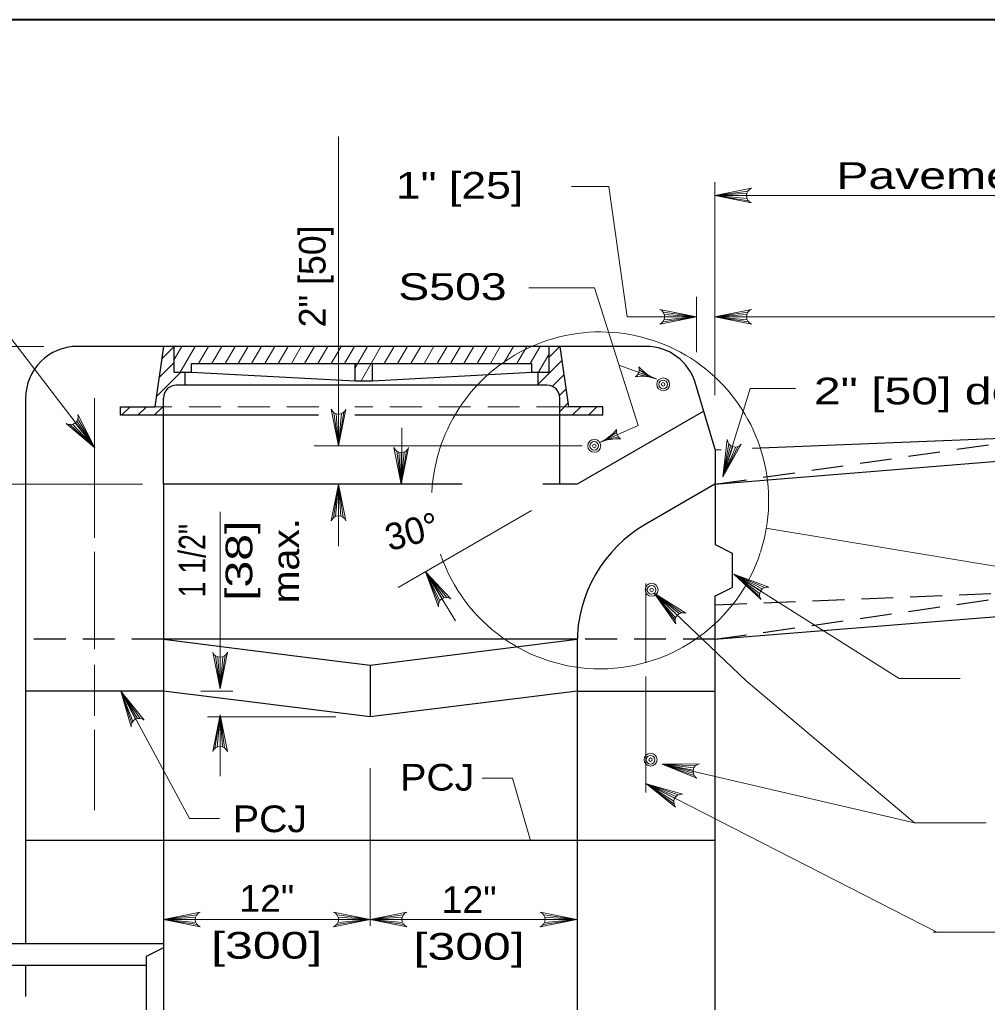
# Model space of a CAD drawing. Extents: x 758.3 to 792.3, y 849.7 to 893.7.
# Drawn here: x 764.35 to 770.01, y 865.44 to 871.19 of the extents above; entities that cross this region are included whole.
import ezdxf
from ezdxf.enums import TextEntityAlignment as Align

# ---------------------------------------------------------------- set-up
doc = ezdxf.new("R2010")
doc.units = 0
doc.header["$LTSCALE"] = 0.062
doc.linetypes.add('MEDIUM_DASHED', pattern=[4.5, 3, -1.5])
doc.layers.add('1', color=7, linetype='Continuous', lineweight=13)

msp = doc.modelspace()

# ---------------------------------------------------------------- linework, layer by layer
at = {"layer": '1', "lineweight": 25}
for p, q in [((760.3205, 871.18817), (791.8205, 871.18817)), ((768.01208, 869.27742), (764.68608, 869.27742)), ((765.19, 869.27742), (765.13967, 868.92475)), ((765.253, 869.12625), (765.253, 869.27742)), ((767.44517, 869.12625), (767.44517, 869.27742)), ((767.50808, 869.27742), (767.5585, 868.92475)), ((765.35383, 869.12625), (765.35383, 869.17667)), ((765.35383, 869.17667), (767.34433, 869.17667)), ((766.31125, 869.07592), (766.31125, 869.17667)), ((766.41208, 869.07592), (766.41208, 869.17667)), ((767.34433, 869.12625), (767.34433, 869.17667)), ((765.316, 869.05067), (765.316, 869.12625)), ((765.35383, 869.12625), (766.31125, 869.07592)), ((766.41208, 869.07592), (767.34433, 869.12625)), ((767.38217, 869.05067), (767.38217, 869.12625)), ((767.4325, 869.05067), (765.26567, 869.05067)), ((766.31125, 869.07592), (766.41208, 869.07592)), ((768.41617, 868.6735), (768.30208, 869.06058)), ((764.38375, 868.97508), (764.38375, 865.78567)), ((765.19, 868.87433), (765.19, 868.97508)), ((767.50808, 868.87433), (767.50808, 868.97508)), ((764.93808, 868.87433), (764.93808, 868.92475)), ((764.93808, 868.92475), (765.13967, 868.92475)), ((766.096, 868.87433), (764.93808, 868.87433)), ((765.19, 868.47125), (765.19, 868.87433)), ((767.76008, 868.87433), (766.30983, 868.87433)), ((767.50808, 868.47125), (767.50808, 868.87433)), ((767.76008, 868.92475), (767.5585, 868.92475)), ((768.34992, 868.89892), (767.60908, 868.47125)), ((767.76008, 868.87433), (767.76008, 868.92475)), ((768.41517, 868.47117), (773.37233, 868.87425)), ((768.6345, 868.68158), (773.37233, 868.87425)), ((768.41517, 868.67267), (768.45258, 868.67425)), ((768.41617, 868.6735), (768.41617, 868.118)), ((765.19, 868.47125), (765.19, 864.39992)), ((766.9375, 868.47125), (765.19, 868.47125)), ((767.60908, 868.47125), (767.40967, 868.47125)), ((768.41517, 868.47117), (768.01208, 868.23842)), ((768.41617, 868.118), (768.516, 868.06817)), ((768.516, 868.06817), (768.516, 867.86658)), ((768.41517, 867.56425), (772.36417, 867.88542)), ((768.41517, 867.81617), (768.516, 867.86658)), ((768.41517, 867.81617), (768.41517, 863.59375)), ((767.60892, 867.56425), (765.19, 867.56425)), ((766.39933, 867.41308), (767.60892, 867.56425)), ((767.60892, 867.54017), (767.60892, 864.39992)), ((766.39933, 867.41308), (766.39933, 867.11075)), ((765.19, 867.26192), (764.38342, 867.26192)), ((766.3995, 867.11075), (765.19, 867.26192)), ((767.60892, 867.26192), (766.39933, 867.11075)), ((767.60892, 867.26192), (768.41525, 867.26192)), ((764.38375, 866.39033), (768.41517, 866.39033)), ((763.47508, 865.78567), (765.19, 865.78567)), ((765.19, 865.7605), (765.08925, 865.71008)), ((763.47333, 865.65958), (765.08925, 865.65958)), ((765.08925, 865.71008), (765.08925, 864.3495))]:
    msp.add_line(p, q, dxfattribs=at)
at = {"layer": '1'}
for p, q in [((766.214, 868.69567), (766.214, 870.5045)), ((767.79483, 870.21275), (767.57708, 870.21275)), ((767.90183, 869.451), (767.79483, 870.21275)), ((768.41517, 868.99158), (768.41517, 870.23767)), ((768.60908, 870.18608), (768.41517, 870.159)), ((768.6025, 870.17267), (768.41517, 870.159)), ((768.6005, 870.159), (768.41517, 870.159)), ((768.60392, 870.14158), (768.41517, 870.159)), ((768.61133, 870.129), (768.41517, 870.159)), ((768.41517, 870.159), (773.37233, 870.159)), ((767.71108, 869.61917), (767.32633, 869.61917)), ((768.30667, 869.24317), (768.30667, 869.56742)), ((767.90183, 869.451), (768.30667, 869.451)), ((768.1105, 869.421), (768.30667, 869.451)), ((768.11275, 869.47808), (768.30667, 869.451)), ((768.11792, 869.43358), (768.30667, 869.451)), ((768.11933, 869.46467), (768.30667, 869.451)), ((768.12133, 869.451), (768.30667, 869.451)), ((768.60908, 869.47808), (768.41517, 869.451)), ((768.6025, 869.46467), (768.41517, 869.451)), ((768.41517, 869.451), (773.1385, 869.451)), ((768.6005, 869.451), (768.41517, 869.451)), ((768.60392, 869.43358), (768.41517, 869.451)), ((768.61133, 869.421), (768.41517, 869.451)), ((764.49067, 869.27742), (762.63192, 869.27742)), ((765.17958, 869.204), (765.253, 869.27742)), ((765.253, 869.19983), (765.29792, 869.27742)), ((765.28817, 869.12625), (765.3755, 869.27742)), ((765.39492, 869.17667), (765.45308, 869.27742)), ((765.47242, 869.17667), (765.53067, 869.27742)), ((765.55008, 869.17667), (765.60833, 869.27742)), ((765.62767, 869.17667), (765.68592, 869.27742)), ((765.70525, 869.17667), (765.7635, 869.27742)), ((765.78283, 869.17667), (765.841, 869.27742)), ((765.8605, 869.17667), (765.91858, 869.27742)), ((765.93808, 869.17667), (765.99625, 869.27742)), ((766.01558, 869.17667), (766.07375, 869.27742)), ((766.09317, 869.17667), (766.15133, 869.27742)), ((766.17075, 869.17667), (766.22892, 869.27742)), ((766.24833, 869.17667), (766.30658, 869.27742)), ((766.31125, 869.1515), (766.38408, 869.27742)), ((766.34533, 869.07592), (766.46167, 869.27742)), ((766.48108, 869.17667), (766.53925, 869.27742)), ((766.55858, 869.17667), (766.61683, 869.27742)), ((766.63625, 869.17667), (766.6945, 869.27742)), ((766.71383, 869.17667), (766.77208, 869.27742)), ((766.79142, 869.17667), (766.84958, 869.27742)), ((766.869, 869.17667), (766.92717, 869.27742)), ((766.94667, 869.17667), (767.00475, 869.27742)), ((767.02417, 869.17667), (767.08242, 869.27742)), ((767.10175, 869.17667), (767.15992, 869.27742)), ((767.17933, 869.17667), (767.23758, 869.27742)), ((767.25692, 869.17667), (767.31508, 869.27742)), ((767.33458, 869.17667), (767.39275, 869.27742)), ((767.44492, 869.21425), (767.50808, 869.27742)), ((767.38308, 869.12625), (767.44517, 869.23367)), ((765.16375, 869.09325), (765.253, 869.1825)), ((767.382, 869.05633), (767.52, 869.19433)), ((768.0735, 869.08675), (767.85358, 869.16842)), ((765.14792, 868.98225), (765.29183, 869.12625)), ((767.46358, 869.04292), (767.53192, 869.11125)), ((767.50808, 868.99242), (767.54367, 869.02808)), ((768.46392, 868.51933), (768.62125, 869.03017)), ((768.62125, 869.03017), (768.88725, 869.03017)), ((764.78692, 868.97508), (764.78692, 868.15833)), ((767.50808, 868.89742), (767.55567, 868.945)), ((764.94492, 868.87433), (764.99533, 868.92475)), ((765.03983, 868.87433), (765.09025, 868.92475)), ((765.135, 868.87433), (765.1855, 868.92475)), ((766.18683, 868.88958), (766.214, 868.69567)), ((766.20025, 868.883), (766.214, 868.69567)), ((766.24392, 868.89183), (766.214, 868.69567)), ((766.23142, 868.88442), (766.214, 868.69567)), ((766.214, 868.881), (766.214, 868.69567)), ((767.581, 868.87533), (767.63033, 868.92475)), ((767.67608, 868.87533), (767.7255, 868.92475)), ((764.64275, 868.82008), (764.78783, 868.68458)), ((764.65725, 868.822), (764.78783, 868.68458)), ((764.673, 868.83008), (764.78783, 868.68458)), ((764.68258, 868.84017), (764.78783, 868.68458)), ((764.689, 868.85367), (764.78783, 868.68458)), ((766.58425, 868.47108), (766.58425, 868.80192)), ((768.49633, 868.708), (768.46167, 868.51525)), ((767.63825, 868.69567), (766.07108, 868.69567)), ((766.55392, 868.66517), (766.581, 868.47125)), ((766.56733, 868.65858), (766.581, 868.47125)), ((766.611, 868.66742), (766.581, 868.47125)), ((766.59842, 868.66), (766.581, 868.47125)), ((766.581, 868.65658), (766.581, 868.47125)), ((768.50708, 868.6975), (768.46167, 868.51525)), ((768.55133, 868.69233), (768.46167, 868.51525)), ((768.5195, 868.69133), (768.46167, 868.51525)), ((768.53708, 868.68917), (768.46167, 868.51525)), ((768.50567, 868.62108), (768.46167, 868.51525)), ((765.06675, 868.47125), (763.33992, 868.47125)), ((766.184, 868.27508), (766.214, 868.47125)), ((766.19658, 868.2825), (766.214, 868.47125)), ((766.214, 868.28592), (766.214, 868.47125)), ((766.22767, 868.28392), (766.214, 868.47125)), ((766.24108, 868.27733), (766.214, 868.47125)), ((766.214, 868.46083), (766.214, 868.10958)), ((765.52067, 867.27408), (765.52067, 868.30892)), ((767.34208, 868.31717), (766.56267, 867.86717)), ((768.71325, 868.21517), (772.67008, 867.555)), ((764.78692, 868.07683), (764.78692, 867.50583)), ((766.81967, 867.80217), (766.72208, 867.95975)), ((766.80667, 867.79008), (766.72208, 867.95975)), ((766.79983, 867.77717), (766.72208, 867.95975)), ((766.83233, 867.80767), (766.72208, 867.95975)), ((766.84725, 867.80917), (766.72208, 867.95975)), ((766.72275, 867.95908), (766.89783, 867.67242)), ((768.68333, 867.84808), (768.52592, 867.94592)), ((768.677, 867.8315), (768.52592, 867.94592)), ((768.67675, 867.81692), (768.52592, 867.94592)), ((768.69225, 867.85867), (768.52592, 867.94592)), ((768.70492, 867.86667), (768.52592, 867.94592)), ((768.01208, 867.89033), (768.01208, 867.42617)), ((768.19467, 867.70575), (768.06042, 867.8335)), ((768.18508, 867.69075), (768.06042, 867.8335)), ((768.18183, 867.67658), (768.06042, 867.8335)), ((768.20558, 867.71433), (768.06042, 867.8335)), ((768.21958, 867.7195), (768.06042, 867.8335)), ((765.49358, 867.468), (765.52067, 867.27408)), ((765.507, 867.46142), (765.52067, 867.27408)), ((765.55067, 867.47025), (765.52067, 867.27408)), ((765.53808, 867.46283), (765.52067, 867.27408)), ((765.52067, 867.45942), (765.52067, 867.27408)), ((764.78692, 867.41508), (764.78692, 867.116)), ((768.01208, 867.346), (768.01208, 866.66817)), ((765.02558, 867.09708), (764.941, 867.262)), ((765.01167, 867.08608), (764.941, 867.262)), ((765.00392, 867.07375), (764.941, 867.262)), ((765.03875, 867.10158), (764.941, 867.262)), ((765.05367, 867.10183), (764.941, 867.262)), ((765.59633, 867.26192), (765.40842, 867.26192)), ((766.19717, 867.11075), (765.44733, 867.11075)), ((765.49067, 866.92675), (765.52067, 867.12292)), ((765.50325, 866.93417), (765.52067, 867.12292)), ((765.52067, 866.76467), (765.52067, 867.12292)), ((765.52067, 866.93758), (765.52067, 867.12292)), ((765.53442, 866.93558), (765.52067, 867.12292)), ((765.54783, 866.929), (765.52067, 867.12292)), ((764.78692, 867.0345), (764.78692, 866.56508)), ((766.3995, 866.81033), (766.3995, 865.88942)), ((768.28817, 866.79975), (768.10608, 866.83392)), ((768.28833, 866.782), (768.10608, 866.83392)), ((768.29333, 866.76825), (768.10608, 866.83392)), ((768.29267, 866.81283), (768.10608, 866.83392)), ((768.30158, 866.82483), (768.10608, 866.83392)), ((768.10608, 866.83392), (769.582, 866.49083)), ((768.01367, 866.721), (769.71275, 865.85208)), ((768.17975, 866.63458), (768.01533, 866.72)), ((768.17475, 866.6175), (768.01533, 866.72)), ((768.17558, 866.60292), (768.01533, 866.72)), ((768.18783, 866.64583), (768.01533, 866.72)), ((768.19992, 866.65467), (768.01533, 866.72)), ((769.582, 866.49083), (770.00233, 866.49083)), ((765.38408, 865.95325), (765.19017, 865.92608)), ((766.20508, 865.95333), (766.399, 865.92617)), ((766.59292, 865.95333), (766.399, 865.92617)), ((767.41358, 865.95325), (767.6075, 865.92608)), ((765.3775, 865.93983), (765.19017, 865.92608)), ((765.3755, 865.92608), (765.19017, 865.92608)), ((765.37892, 865.90867), (765.19017, 865.92608)), ((765.38633, 865.89617), (765.19017, 865.92608)), ((765.19017, 865.92608), (767.6075, 865.92608)), ((766.20283, 865.89617), (766.399, 865.92617)), ((766.21025, 865.90875), (766.399, 865.92617)), ((766.21167, 865.93992), (766.399, 865.92617)), ((766.21367, 865.92617), (766.399, 865.92617)), ((766.58633, 865.93992), (766.399, 865.92617)), ((766.58433, 865.92617), (766.399, 865.92617)), ((766.58775, 865.90875), (766.399, 865.92617)), ((766.59517, 865.89617), (766.399, 865.92617)), ((767.41133, 865.89617), (767.6075, 865.92608)), ((767.41875, 865.90867), (767.6075, 865.92608)), ((767.42017, 865.93983), (767.6075, 865.92608)), ((767.42217, 865.92608), (767.6075, 865.92608)), ((769.69142, 865.85208), (770.11175, 865.85208))]:
    msp.add_line(p, q, dxfattribs=at)
at = {"layer": '1', "linetype": 'MEDIUM_DASHED'}
for p, q in [((766.09775, 868.92475), (765.13967, 868.92475)), ((767.5585, 868.92475), (766.30983, 868.92475))]:
    msp.add_line(p, q, dxfattribs=at)
at = {"layer": '1', "linetype": 'MEDIUM_DASHED', "lineweight": 25}
for p, q in [((768.41517, 868.47117), (770.22933, 868.73317)), ((768.41517, 867.76575), (771.35858, 867.88542)), ((768.41517, 867.56425), (770.22933, 867.82625)), ((765.19, 867.56425), (764.38092, 867.56425)), ((768.41517, 867.56425), (767.60892, 867.56425)), ((764.38375, 865.6525), (764.38375, 865.47483))]:
    msp.add_line(p, q, dxfattribs=at)
at = {"layer": '1', "lineweight": 40}
msp.add_lwpolyline([(760.3205, 871.18817), (791.8205, 871.18817), (791.8205, 850.18817), (760.3205, 850.18817)], close=True, dxfattribs=at)
at = {"layer": '1'}
for points in [[(768.62933, 870.11617), (768.41517, 870.159), (768.62933, 870.20183)], [(764.78783, 868.68458), (763.85467, 869.90025), (763.401, 869.90025)], [(767.74192, 868.71533), (767.96558, 868.81417), (767.71108, 869.61917)], [(768.0925, 869.40817), (768.30667, 869.451), (768.0925, 869.49383)], [(768.62933, 869.40817), (768.41517, 869.451), (768.62933, 869.49383)], [(764.62158, 868.82625), (764.78783, 868.68458), (764.68883, 868.87925)], [(766.25683, 868.90983), (766.214, 868.69567), (766.17117, 868.90983)], [(768.56917, 868.70542), (768.46167, 868.51525), (768.48775, 868.73217)], [(766.62383, 868.68542), (766.581, 868.47125), (766.53817, 868.68542)], [(766.17117, 868.25708), (766.214, 868.47125), (766.25683, 868.25708)], [(766.79842, 867.75508), (766.72208, 867.95975), (766.87125, 867.80017)], [(768.68525, 867.7965), (768.52592, 867.94592), (768.73042, 867.86925)], [(768.52592, 867.94592), (769.49258, 867.33583), (769.85033, 867.33583)], [(768.06042, 867.8335), (768.59825, 867.32158), (769.582, 866.49083)], [(768.186, 867.65483), (768.06042, 867.8335), (768.24508, 867.71692)], [(765.5635, 867.48825), (765.52067, 867.27408), (765.47783, 867.48825)], [(765.00067, 867.05192), (764.941, 867.262), (765.07692, 867.091)], [(764.941, 867.262), (765.34225, 866.5155), (765.51717, 866.5155)], [(765.47783, 866.90875), (765.52067, 867.12292), (765.5635, 866.90875)], [(768.30867, 866.75233), (768.10608, 866.83392), (768.32442, 866.8365)], [(767.33425, 866.39392), (767.23058, 866.7525), (767.05483, 866.75175)], [(768.18567, 866.58325), (768.01533, 866.72), (768.22508, 866.65933)], [(765.40433, 865.88325), (765.19017, 865.92608), (765.40433, 865.969)], [(766.18483, 865.88333), (766.399, 865.92617), (766.18483, 865.969)], [(766.61317, 865.88333), (766.399, 865.92617), (766.61317, 865.969)], [(767.39333, 865.88325), (767.6075, 865.92608), (767.39333, 865.969)]]:
    msp.add_lwpolyline(points, dxfattribs=at)
at = {"layer": '1', "lineweight": 25}
for points in [[(765.253, 869.12625), (765.316, 869.12625), (765.35383, 869.12625)], [(767.34433, 869.12625), (767.38217, 869.12625), (767.44517, 869.12625)], [(765.19, 867.56425), (765.9885, 867.4645), (766.39933, 867.41308)]]:
    msp.add_lwpolyline(points, dxfattribs=at)
at = {"layer": '1'}
for centre, start, end in [((768.64665, 870.15902), 112.08782, 247.91395), ((768.07517, 869.45103), 292.08605, 67.91218), ((768.64665, 869.45103), 112.08782, 247.91395), ((764.6445, 868.86636), 240.34782, 16.17395), ((766.21392, 868.92713), 202.08782, 337.91395), ((768.53381, 868.73521), 183.91048, 319.73661), ((766.58098, 868.70271), 202.08782, 337.91395), ((766.21402, 868.23978), 22.08782, 157.91395), ((768.72254, 867.82381), 80.23992, 216.06604), ((766.84398, 867.76294), 53.85151, 189.67764), ((768.22811, 867.67398), 68.49887, 204.325), ((765.52064, 867.50556), 202.08782, 337.91395), ((765.04672, 867.05607), 49.25632, 185.08245), ((765.52073, 866.89146), 22.08782, 157.91395), ((768.33354, 866.79127), 101.44909, 237.27522), ((768.22075, 866.61335), 84.64837, 220.47449), ((765.42162, 865.92617), 112.08782, 247.91395), ((766.16752, 865.92622), 292.08605, 67.91218), ((766.63045, 865.92622), 112.08782, 247.91395), ((767.37605, 865.92617), 292.08605, 67.91218)]:
    msp.add_arc(centre, 0.04623, start, end, dxfattribs=at)
for centre, major_axis, ratio, start_param, end_param in [((767.74416, 868.37681), (0.98544, 0), 0.999895, 5.9710746, 9.3780837), ((767.92268, 869.14265), (0.04999, 0), 0.999895, 5.278256, 6.5772462), ((767.98345, 868.83931), (-0.26337, 0), 0.999895, 4.3633429, 4.8416995), ((768.02925, 868.95995), (-0.25349, 0.08803), 0.500063, 4.7097138, 5.1481812), ((768.16943, 869.33727), (-0.26836, 0), 0.999895, 0.7359679, 1.2047992), ((768.12263, 869.21149), (0.24955, -0.09866), 0.500066, 4.2768504, 4.7127126), ((767.68524, 868.8371), (0.24311, 0.11361), 0.500071, 4.7098111, 5.1482786), ((767.63395, 868.95551), (0.26337, 0), 0.999895, 5.1348728, 5.6132294), ((767.88903, 868.78042), (-0.04999, 0), 0.999895, 6.049786, 7.3487762), ((767.7937, 868.59168), (-0.24769, -0.10324), 0.500068, 4.2769482, 4.7128104), ((767.84786, 868.46889), (-0.26836, 0), 0.999895, 4.6490906, 5.1179219), ((767.74416, 868.37681), (0.98544, 0), 0.999895, 3.467441, 5.9662313)]:
    msp.add_ellipse(centre, major_axis=major_axis, ratio=ratio, start_param=start_param, end_param=end_param, dxfattribs=at)
at = {"layer": '1', "lineweight": 25}
for centre, major_axis, start_param, end_param in [((764.68611, 868.97512), (-0.30236, 0), 4.712389, 6.2831853), ((768.01208, 868.97512), (0.30236, 0), 0.286601, 1.5707963), ((765.26565, 868.97512), (-0.07559, 0), 4.7123889, 6.2831852), ((767.43253, 868.97512), (0.07559, 0), 6.2831852, 7.8539815), ((768.41519, 867.54021), (-0.80629, 0), 5.2359943, 6.2831853)]:
    msp.add_ellipse(centre, major_axis=major_axis, ratio=0.999895, start_param=start_param, end_param=end_param, dxfattribs=at)
at = {"layer": '1'}
for centre, major_axis in [((768.11283, 869.05523), (0.03779, 0)), ((768.11283, 869.05523), (0.0252, 0)), ((768.11283, 869.05523), (0.01008, 0)), ((767.70969, 868.69567), (0.03779, 0)), ((767.70969, 868.69567), (0.0252, 0)), ((767.70969, 868.69567), (0.01008, 0)), ((768.0451, 867.85359), (0.03779, 0)), ((768.0451, 867.85359), (0.0252, 0)), ((768.0451, 867.85359), (0.01008, 0)), ((768.03895, 866.86025), (0.03779, 0)), ((768.03895, 866.86025), (0.0252, 0)), ((768.03895, 866.86025), (0.01008, 0))]:
    msp.add_ellipse(centre, major_axis=major_axis, ratio=0.999895, dxfattribs=at)

# ---------------------------------------------------------------- texts
for s, width, p in [('Pavement or paved shoulder', 1.35, (770.92575, 870.1985)), ('12"', 1.05, (765.79379, 865.97092)), ('12"', 1.05, (766.97762, 865.9645)), ('[300]', 1.4, (765.79387, 865.69692)), ('[300]', 1.4, (766.97771, 865.6905))]:
    msp.add_text(s, height=0.156, dxfattribs=dict(at, width=width)).set_placement(p, align=Align.CENTER)
for s, width, p in [('1" [25]', 1.25, (766.54925, 870.1415)), ('S503', 1.3, (766.5635, 869.549)), ('2" [50] depression', 1.35, (768.99408, 868.93825)), ('PCJ', 1.1, (766.57475, 866.67958)), ('PCJ', 1.1, (765.59625, 866.4365))]:
    msp.add_text(s, height=0.156, dxfattribs=dict(at, width=width)).set_placement(p)
for s, rotation, p in [('2" [50]', 90, (766.13792, 869.38858)), ('30°', 14.998, (766.51108, 868.07908))]:
    msp.add_text(s, height=0.156, rotation=rotation, dxfattribs=at).set_placement(p)
for s, width, p in [('max.', 1.1, (765.9835, 868.02387)), ('1 1/2"', 0.8, (765.4355, 868.02383)), ('[38]', 1.35, (765.7095, 868.02379))]:
    msp.add_text(s, height=0.156, rotation=90, dxfattribs=dict(at, width=width)).set_placement(p, align=Align.CENTER)

doc.saveas('drawing.dxf')
